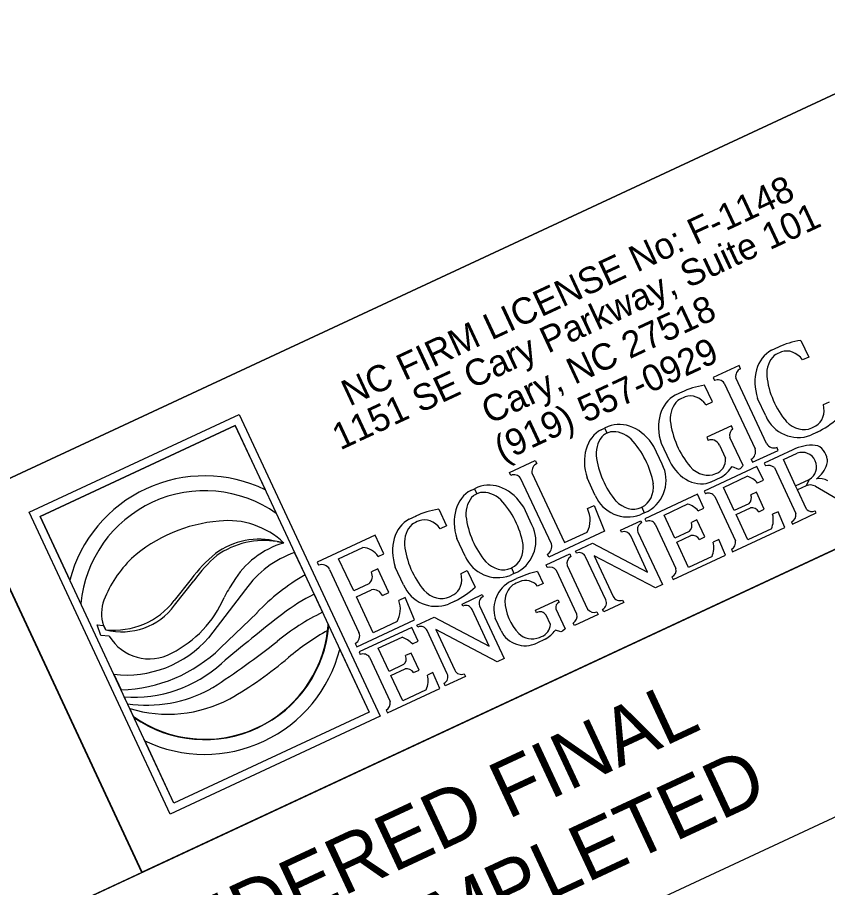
# Model space of a CAD drawing. Extents: x 2216017 to 2218023, y 761241 to 762957.
# Drawn here: x 2217518.1 to 2217596.5, y 762718.7 to 762803 of the extents above; entities that cross this region are included whole.
import ezdxf

# ---------------------------------------------------------------- set-up
doc = ezdxf.new("R2010")
doc.units = 0
for name, color, linetype in [('Exist Horizontal Alignment Tick Label', 7, 'Continuous'), ('Sheet Block Title CELL', 7, 'Continuous'), ('Sheet Plan And Profile CELL', 7, 'Continuous'), ('Sheet Sticker Exception Certification CELL', 7, 'Continuous'), ('Stewart Logo', 7, 'Continuous')]:
    doc.layers.add(name, color=color, linetype=linetype)

msp = doc.modelspace()

# ---------------------------------------------------------------- linework, layer by layer
at = {"layer": 'Sheet Block Title CELL'}
for p, q in [((2217593.973, 762771.693), (2217594.724, 762770.082)), ((2217591.132, 762770.738), (2217591.836, 762771.066)), ((2217594.724, 762770.082), (2217594.128, 762769.804)), ((2217587.978, 762769.257), (2217585.465, 762768.085)), ((2217588.12, 762768.952), (2217587.978, 762769.257)), ((2217585.393, 762765.73), (2217584.642, 762767.342)), ((2217585.465, 762768.085), (2217585.594, 762767.808)), ((2217586.552, 762767.56), (2217589.53, 762761.175)), ((2217590.631, 762761.69), (2217587.654, 762768.074)), ((2217582.505, 762766.714), (2217581.801, 762766.386)), ((2217584.797, 762765.453), (2217585.393, 762765.73)), ((2217590.568, 762764.379), (2217589.775, 762766.08)), ((2217596.146, 762765.477), (2217596.742, 762765.755)), ((2217519.268, 762755.039), (2217539.597, 762764.519)), ((2217539.597, 762764.519), (2217553.231, 762735.281)), ((2217520.314, 762754.648), (2217539.204, 762763.457)), ((2217539.204, 762763.457), (2217520.314, 762754.648)), ((2217539.204, 762763.457), (2217552.161, 762735.67)), ((2217542.118, 762757.208), (2217539.204, 762763.457)), ((2217574.626, 762763.04), (2217574.964, 762763.198)), ((2217575.303, 762763.356), (2217574.964, 762763.198)), ((2217574.964, 762763.198), (2217575.196, 762762.701)), ((2217574.964, 762763.198), (2217575.196, 762762.701)), ((2217587.241, 762763.423), (2217584.851, 762762.309)), ((2217587.39, 762763.102), (2217587.241, 762763.423)), ((2217595.016, 762763.217), (2217595.425, 762763.419)), ((2217584.851, 762762.309), (2217585.001, 762761.988)), ((2217588.366, 762759.561), (2217587.096, 762762.284)), ((2217595.542, 762762.798), (2217594.919, 762762.508)), ((2217580.536, 762759.701), (2217579.743, 762761.402)), ((2217580.444, 762761.728), (2217581.237, 762760.028)), ((2217586.09, 762761.552), (2217586.674, 762760.299)), ((2217589.289, 762759.882), (2217591.777, 762761.042)), ((2217593.196, 762761.095), (2217590.419, 762759.801)), ((2217591.777, 762761.042), (2217591.64, 762761.334)), ((2217592.267, 762760.14), (2217593.591, 762760.758)), ((2217565.741, 762758.888), (2217568.254, 762760.059)), ((2217568.254, 762760.059), (2217568.396, 762759.754)), ((2217589.153, 762760.174), (2217589.289, 762759.882)), ((2217590.419, 762759.801), (2217590.541, 762759.539)), ((2217593.449, 762757.605), (2217592.267, 762760.14)), ((2217565.87, 762758.61), (2217565.741, 762758.888)), ((2217567.93, 762758.877), (2217571.089, 762752.103)), ((2217589.714, 762759.472), (2217584.613, 762757.093)), ((2217587.298, 762759.481), (2217587.92, 762759.203)), ((2217587.92, 762759.203), (2217588.105, 762759.289)), ((2217588.105, 762759.289), (2217588.366, 762759.561)), ((2217590.334, 762758.141), (2217589.714, 762759.472)), ((2217591.4, 762759.365), (2217593.475, 762754.914)), ((2217569.806, 762751.978), (2217566.828, 762758.363)), ((2217574.061, 762756.682), (2217573.268, 762758.382)), ((2217585.276, 762757.989), (2217586.26, 762758.448)), ((2217586.474, 762757.458), (2217588.773, 762758.53)), ((2217589.772, 762757.879), (2217590.334, 762758.141)), ((2217593.449, 762757.605), (2217594.773, 762758.222)), ((2217594.773, 762758.222), (2217594.465, 762757.6)), ((2217594.773, 762758.222), (2217594.465, 762757.6)), ((2217562.021, 762757.163), (2217562.36, 762757.321)), ((2217562.698, 762757.478), (2217562.36, 762757.321)), ((2217562.36, 762757.321), (2217562.592, 762756.823)), ((2217562.36, 762757.321), (2217562.592, 762756.823)), ((2217587.517, 762755.219), (2217586.474, 762757.458)), ((2217593.632, 762757.212), (2217593.449, 762757.605)), ((2217593.632, 762757.212), (2217593.449, 762757.605)), ((2217594.465, 762757.6), (2217593.632, 762757.212)), ((2217594.497, 762755.358), (2217593.632, 762757.212)), ((2217595.376, 762757.558), (2217597.865, 762756.104)), ((2217583.955, 762756.787), (2217578.855, 762754.408)), ((2217584.576, 762755.456), (2217583.955, 762756.787)), ((2217584.613, 762757.093), (2217584.734, 762756.835)), ((2217585.625, 762756.577), (2217587.628, 762752.282)), ((2217589.651, 762756.994), (2217589.119, 762756.745)), ((2217590.421, 762755.341), (2217589.651, 762756.994)), ((2217567.932, 762753.824), (2217567.139, 762755.524)), ((2217573.294, 762755.395), (2217573.953, 762755.702)), ((2217573.953, 762755.702), (2217574.966, 762753.203)), ((2217578.51, 762755.52), (2217578.538, 762755.534)), ((2217578.552, 762755.54), (2217578.793, 762754.988)), ((2217578.552, 762755.54), (2217578.793, 762754.988)), ((2217580.715, 762754.772), (2217583.014, 762755.845)), ((2217588.918, 762755.873), (2217587.517, 762755.219)), ((2217532.902, 762725.801), (2217519.268, 762755.039)), ((2217533.271, 762726.862), (2217520.314, 762754.648)), ((2217520.314, 762754.648), (2217523.2, 762748.458)), ((2217556.057, 762754.382), (2217556.761, 762754.71)), ((2217556.761, 762754.71), (2217556.646, 762754.656)), ((2217558.898, 762755.337), (2217559.649, 762753.726)), ((2217578.793, 762754.988), (2217578.413, 762754.81)), ((2217578.793, 762754.988), (2217579.173, 762755.165)), ((2217581.759, 762752.534), (2217580.715, 762754.772)), ((2217584.013, 762755.194), (2217584.576, 762755.456)), ((2217587.702, 762754.824), (2217589.075, 762755.464)), ((2217588.843, 762752.376), (2217587.702, 762754.824)), ((2217589.896, 762755.096), (2217590.421, 762755.341)), ((2217591.764, 762755.094), (2217591.231, 762754.846)), ((2217592.417, 762753.563), (2217591.764, 762755.094)), ((2217593.154, 762753.907), (2217595.455, 762754.98)), ((2217595.455, 762754.98), (2217595.355, 762755.194)), ((2217576.497, 762753.309), (2217578.453, 762754.221)), ((2217578.453, 762754.221), (2217578.544, 762754.025)), ((2217578.855, 762754.408), (2217578.975, 762754.15)), ((2217579.867, 762753.892), (2217581.87, 762749.597)), ((2217583.893, 762754.309), (2217583.36, 762754.06)), ((2217584.663, 762752.656), (2217583.893, 762754.309)), ((2217593.054, 762754.121), (2217593.154, 762753.907)), ((2217559.649, 762753.726), (2217559.054, 762753.448)), ((2217574.966, 762753.203), (2217569.565, 762750.685)), ((2217571.089, 762752.103), (2217573.286, 762753.127)), ((2217576.589, 762753.113), (2217576.497, 762753.309)), ((2217578.189, 762753.128), (2217580.563, 762748.036)), ((2217583.16, 762753.187), (2217581.759, 762752.534)), ((2217587.359, 762751.205), (2217592.417, 762753.563)), ((2217591.117, 762753.436), (2217588.843, 762752.376)), ((2217543.903, 762752.067), (2217543.276, 762752.201)), ((2217543.276, 762752.201), (2217543.903, 762752.067)), ((2217552.744, 762752.827), (2217547.139, 762750.214)), ((2217553.587, 762751.018), (2217552.744, 762752.827)), ((2217561.457, 762750.805), (2217560.664, 762752.505)), ((2217579.129, 762749.238), (2217577.485, 762752.764)), ((2217581.944, 762752.138), (2217583.316, 762752.779)), ((2217583.085, 762749.691), (2217581.944, 762752.138)), ((2217584.137, 762752.411), (2217584.663, 762752.656)), ((2217586.005, 762752.409), (2217585.473, 762752.161)), ((2217586.659, 762750.878), (2217586.005, 762752.409)), ((2217549.213, 762750.545), (2217551.542, 762751.631)), ((2217572.137, 762751.275), (2217573.79, 762752.047)), ((2217572.228, 762751.079), (2217572.137, 762751.275)), ((2217573.79, 762752.047), (2217579.129, 762749.238)), ((2217587.239, 762751.463), (2217587.359, 762751.205)), ((2217545.96, 762748.97), (2217544.946, 762751.143)), ((2217550.67, 762747.421), (2217549.213, 762750.545)), ((2217553.027, 762750.757), (2217553.587, 762751.018)), ((2217569.295, 762749.95), (2217571.586, 762751.019)), ((2217569.565, 762750.685), (2217569.429, 762750.977)), ((2217571.586, 762751.019), (2217571.704, 762750.766)), ((2217575.073, 762746.551), (2217573.124, 762750.731)), ((2217579.882, 762747.718), (2217573.957, 762750.835)), ((2217573.957, 762750.835), (2217575.796, 762746.89)), ((2217581.601, 762748.52), (2217586.659, 762750.878)), ((2217585.359, 762750.751), (2217583.085, 762749.691)), ((2217547.139, 762750.214), (2217547.278, 762749.917)), ((2217555.493, 762748.024), (2217554.7, 762749.724)), ((2217565.905, 762749.643), (2217565.934, 762749.657)), ((2217565.948, 762749.663), (2217566.188, 762749.11)), ((2217565.948, 762749.663), (2217566.188, 762749.11)), ((2217569.412, 762749.698), (2217569.295, 762749.95)), ((2217571.34, 762749.883), (2217573.304, 762745.672)), ((2217548.33, 762749.508), (2217551.18, 762743.397)), ((2217552.993, 762749.565), (2217552.38, 762749.279)), ((2217554.066, 762747.263), (2217552.993, 762749.565)), ((2217561.071, 762749.122), (2217561.667, 762749.4)), ((2217561.667, 762749.4), (2217562.418, 762747.788)), ((2217566.188, 762749.11), (2217565.808, 762748.933)), ((2217566.188, 762749.11), (2217566.568, 762749.287)), ((2217568.464, 762749.299), (2217569, 762748.148)), ((2217572.276, 762745.175), (2217570.299, 762749.415)), ((2217581.48, 762748.778), (2217581.601, 762748.52)), ((2217534.947, 762748.57), (2217533.3, 762746.483)), ((2217533.336, 762746.03), (2217535.191, 762748.411)), ((2217552.125, 762748.099), (2217550.67, 762747.421)), ((2217565.909, 762748.372), (2217566.444, 762748.621)), ((2217569, 762748.148), (2217568.459, 762747.896)), ((2217580.563, 762748.036), (2217579.882, 762747.718)), ((2217540.203, 762747.561), (2217536.63, 762742.893)), ((2217546.829, 762747.105), (2217547.646, 762745.354)), ((2217550.934, 762746.855), (2217552.389, 762747.533)), ((2217553.453, 762746.977), (2217554.066, 762747.263)), ((2217559.941, 762746.862), (2217560.35, 762747.064)), ((2217561.16, 762746.157), (2217563.116, 762747.069)), ((2217563.116, 762747.069), (2217563.207, 762746.873)), ((2217552.556, 762743.377), (2217550.934, 762746.855)), ((2217555.647, 762746.783), (2217555.039, 762746.5)), ((2217556.566, 762744.631), (2217555.647, 762746.783)), ((2217560.467, 762746.442), (2217559.844, 762746.152)), ((2217568.271, 762745.545), (2217570.443, 762746.557)), ((2217570.443, 762746.557), (2217570.55, 762746.328)), ((2217576.818, 762746.289), (2217574.877, 762745.384)), ((2217576.699, 762746.543), (2217576.818, 762746.289)), ((2217561.251, 762745.961), (2217561.16, 762746.157)), ((2217563.792, 762742.086), (2217562.147, 762745.612)), ((2217562.851, 762745.976), (2217565.226, 762740.884)), ((2217568.378, 762745.315), (2217568.271, 762745.545)), ((2217570.232, 762745.694), (2217571.139, 762743.749)), ((2217574.214, 762745.383), (2217574.332, 762745.13)), ((2217574.877, 762745.384), (2217574.758, 762745.638)), ((2217537.78, 762741.901), (2217541.31, 762745.316)), ((2217550.962, 762742.017), (2217556.566, 762744.631)), ((2217556.799, 762744.123), (2217558.453, 762744.895)), ((2217558.453, 762744.895), (2217563.792, 762742.086)), ((2217564.941, 762743.567), (2217564.375, 762744.781)), ((2217569.715, 762744.175), (2217569.298, 762745.07)), ((2217574.332, 762745.13), (2217572.041, 762744.062)), ((2217526.199, 762743.094), (2217525.851, 762744.132)), ((2217525.851, 762744.132), (2217526.445, 762744.08)), ((2217526.671, 762743.669), (2217526.445, 762744.08)), ((2217526.445, 762744.08), (2217526.671, 762743.669)), ((2217556.292, 762743.887), (2217551.192, 762741.509)), ((2217554.868, 762744.455), (2217552.556, 762743.377)), ((2217556.913, 762742.557), (2217556.292, 762743.887)), ((2217556.891, 762743.927), (2217556.799, 762744.123)), ((2217564.545, 762740.566), (2217558.619, 762743.683)), ((2217558.619, 762743.683), (2217560.459, 762739.738)), ((2217571.139, 762743.749), (2217570.891, 762743.525)), ((2217572.041, 762744.062), (2217571.923, 762744.314)), ((2217527.01, 762743.052), (2217526.199, 762743.094)), ((2217553.052, 762741.873), (2217555.351, 762742.945)), ((2217559.736, 762739.399), (2217557.787, 762743.579)), ((2217568.649, 762742.917), (2217568.86, 762743.001)), ((2217570.723, 762743.447), (2217570.199, 762743.609)), ((2217570.891, 762743.525), (2217570.723, 762743.447)), ((2217550.817, 762742.327), (2217550.962, 762742.017)), ((2217556.35, 762742.294), (2217556.913, 762742.557)), ((2217569.215, 762742.758), (2217568.389, 762742.372)), ((2217549.273, 762741.865), (2217552.161, 762735.67)), ((2217551.192, 762741.509), (2217551.312, 762741.25)), ((2217554.096, 762739.635), (2217553.052, 762741.873)), ((2217556.23, 762741.409), (2217555.697, 762741.161)), ((2217557, 762739.757), (2217556.23, 762741.409)), ((2217552.204, 762740.993), (2217554.207, 762736.697)), ((2217565.226, 762740.884), (2217564.545, 762740.566)), ((2217555.497, 762740.288), (2217554.096, 762739.635)), ((2217554.28, 762739.239), (2217555.653, 762739.879)), ((2217556.474, 762739.512), (2217557, 762739.757)), ((2217558.342, 762739.51), (2217557.809, 762739.261)), ((2217558.996, 762737.979), (2217558.342, 762739.51)), ((2217527.448, 762739.349), (2217528.163, 762737.835)), ((2217555.422, 762736.791), (2217554.28, 762739.239)), ((2217561.48, 762739.137), (2217559.539, 762738.232)), ((2217561.362, 762739.391), (2217561.48, 762739.137)), ((2217553.938, 762735.62), (2217558.996, 762737.979)), ((2217557.696, 762737.852), (2217555.422, 762736.791)), ((2217559.539, 762738.232), (2217559.421, 762738.486)), ((2217528.778, 762736.496), (2217528.466, 762737.166)), ((2217529.353, 762735.264), (2217528.995, 762736.032)), ((2217553.231, 762735.281), (2217532.902, 762725.801)), ((2217552.161, 762735.67), (2217533.271, 762726.862)), ((2217552.161, 762735.67), (2217533.271, 762726.862)), ((2217553.817, 762735.878), (2217553.938, 762735.62)), ((2217533.271, 762726.862), (2217530.41, 762732.997))]:
    msp.add_line(p, q, dxfattribs=at)
for centre, radius, start, end in [((2217588.493, 762768.191), 0.847, 116.12075, 187.92747), ((2217585.916, 762767.075), 0.8, 37.30893, 113.74227), ((2217593.713, 762765.696), 3.409, 202.72337, 290.72862), ((2217592.073, 762769.912), 7.915, 295.99068, 313.21702), ((2217591.353, 762762.127), 0.844, 211.20618, 289.93946), ((2217595.046, 762757.445), 4.093, 85.64607, 116.88413), ((2217595.252, 762760.447), 1.084, 33.14024, 84.43273), ((2217588.731, 762760.904), 0.844, 300.06054, 18.72851), ((2217594.084, 762759.444), 1.403, 299.4241, 110.5759), ((2217594.428, 762759.796), 2.132, 10.58297, 35.67988), ((2217568.769, 762758.994), 0.847, 116.12075, 187.92747), ((2217577.506, 762758.139), 3.409, 299.27138, 27.27663), ((2217593.589, 762760.671), 3.054, 308.30868, 341.19279), ((2217595.529, 762760.023), 1.009, 340.54557, 9.405), ((2217590.816, 762758.694), 0.889, 48.98938, 108.04248), ((2217536.248, 762745.082), 13.488, 64.25416, 165.43722), ((2217566.192, 762757.878), 0.8, 37.30893, 113.74227), ((2217588.023, 762756.287), 2.364, 42.31695, 71.52263), ((2217595.772, 762756.652), 1.649, 61.4512, 100.11922), ((2217594.88, 762756.71), 0.982, 59.70431, 115), ((2217536.248, 762745.082), 12.045, 54.87011, 174.69223), ((2217577.206, 762757.999), 3.409, 202.72337, 290.72862), ((2217585.033, 762756.2), 0.702, 32.52547, 115.21556), ((2217588.413, 762756.448), 0.766, 311.2755, 22.86037), ((2217582.265, 762753.602), 2.364, 42.31695, 71.52263), ((2217589.198, 762754.639), 0.834, 33.27091, 98.51806), ((2217571.077, 762754.268), 2.487, 332.69023, 26.93099), ((2217589.009, 762754.315), 2.284, 337.36137, 13.42705), ((2217592.796, 762754.766), 0.695, 291.81671, 12.25698), ((2217595.027, 762755.807), 0.695, 220.28121, 298.18329), ((2217538.86, 762739.571), 14.667, 94.78512, 131.409), ((2217538.513, 762746.455), 7.781, 46.15126, 96.46785), ((2217564.901, 762752.261), 3.409, 299.27138, 27.27663), ((2217578.854, 762753.383), 0.713, 115.75062, 200.94573), ((2217579.274, 762753.514), 0.702, 32.52547, 115.21556), ((2217582.655, 762753.763), 0.766, 311.2755, 22.86037), ((2217576.854, 762752.469), 0.696, 24.91789, 112.41505), ((2217541.494, 762745.38), 7.05, 75.35831, 126.6336), ((2217541.996, 762744.358), 7.947, 80.73048, 125.15374), ((2217583.44, 762751.953), 0.834, 33.27091, 98.51806), ((2217583.251, 762751.63), 2.284, 337.36137, 13.42705), ((2217586.894, 762752.129), 0.75, 297.36509, 11.76665), ((2217546.193, 762744.054), 8.333, 105.94703, 149.59091), ((2217551.478, 762749.822), 1.81, 31.10841, 87.96506), ((2217569.007, 762751.707), 0.844, 300.06054, 18.72851), ((2217537.495, 762742.138), 11.858, 134.67076, 158.22167), ((2217545.445, 762740.957), 12.968, 128.98209, 144.05119), ((2217546.986, 762739.893), 14.55, 131.10523, 144.16107), ((2217548.158, 762741.959), 9.729, 109.27295, 144.84349), ((2217564.601, 762752.122), 3.409, 202.72337, 290.72862), ((2217572.111, 762750.082), 0.796, 120.76553, 194.44607), ((2217572.494, 762750.436), 0.696, 24.91789, 112.41505), ((2217547.588, 762749.156), 0.822, 25.36228, 112.17361), ((2217569.658, 762748.938), 0.799, 36.6163, 107.89411), ((2217581.136, 762749.444), 0.75, 297.36509, 11.76665), ((2217555.658, 762731.84), 19.685, 119.518, 136.79686), ((2217551.521, 762748.847), 0.961, 308.95151, 26.71522), ((2217570.29, 762740.509), 8.978, 101.73903, 115.36722), ((2217549.738, 762740.896), 13.023, 145.49999, 153.10055), ((2217558.638, 762749.341), 3.409, 202.72337, 290.72862), ((2217567.303, 762745.653), 3.056, 117.14862, 196.57596), ((2217567.401, 762746.365), 2.099, 128.90312, 177.34012), ((2217569.049, 762742.824), 5.965, 112.84839, 119.82308), ((2217567.3, 762746.906), 1.524, 40.48108, 111.82605), ((2217557.002, 762727.432), 22.148, 117.34292, 126.57405), ((2217552.574, 762746.59), 0.961, 23.77933, 101.04849), ((2217556.998, 762753.556), 7.915, 295.99068, 313.21702), ((2217530.021, 762745.254), 3.764, 160.058, 198.18149), ((2217527.461, 762751.023), 7.396, 263.86957, 322.13459), ((2217528.184, 762751.076), 10.826, 296.69632, 336.66704), ((2217552.792, 762745.658), 2.399, 329.89667, 20.53981), ((2217563.517, 762746.231), 0.713, 115.75062, 200.94573), ((2217570.17, 762746.656), 4.87, 182.28071, 223.62041), ((2217570.791, 762745.811), 0.571, 114.91648, 191.84717), ((2217574.442, 762746.258), 0.696, 297.03543, 25.08211), ((2217576.428, 762747.184), 0.696, 204.91789, 292.96457), ((2217528.251, 762749.797), 6.328, 255.53701, 323.46219), ((2217557.564, 762725.105), 22.547, 116.09717, 129.36003), ((2217561.517, 762745.317), 0.696, 24.91789, 112.41505), ((2217568.716, 762744.737), 0.67, 29.75047, 120.35254), ((2217573.952, 762746.135), 0.796, 215.55393, 289.23447), ((2217657.947, 762598.351), 186.006, 127.85343, 130.20923), ((2217571.499, 762744.991), 0.799, 302.10589, 13.3837), ((2217536.248, 762745.082), 12.063, 235.30777, 355.12989), ((2217536.275, 762745.017), 11.96, 353.1944, 355.87724), ((2217557.156, 762743.284), 0.696, 24.91789, 112.41505), ((2217568.361, 762744.264), 1.358, 291.5697, 356.2289), ((2217530.88, 762745.347), 4.5, 210.66616, 298.79825), ((2217528.661, 762749.874), 10.595, 263.42388, 318.77767), ((2217536.275, 762745.017), 11.96, 234.63413, 353.1944), ((2217560.254, 762722.097), 24.675, 119.37453, 130.11181), ((2217550.433, 762743.054), 0.822, 297.82639, 24.63772), ((2217554.602, 762740.702), 2.364, 42.31695, 71.52263), ((2217567.263, 762744.697), 2.583, 205.95183, 295.84129), ((2217567.949, 762744.701), 1.916, 227.11766, 291.43228), ((2217567.396, 762745.855), 3.592, 300.4223, 321.30188), ((2217494.327, 762804.233), 78.748, 302.84485, 308.42277), ((2217527.721, 762752.287), 14.459, 271.75125, 314.08391), ((2217536.248, 762745.082), 13.488, 244.56278, 345.74584), ((2217551.611, 762740.615), 0.702, 32.52547, 115.21556), ((2217554.992, 762740.863), 0.766, 311.2755, 22.86037), ((2217529.382, 762749.77), 12.637, 265.84198, 312.16072), ((2217520.22, 762769.247), 37.179, 299.76476, 310.48222), ((2217555.777, 762739.054), 0.834, 33.27091, 98.51806), ((2217561.09, 762740.032), 0.696, 204.91789, 292.96457), ((2217555.588, 762738.731), 2.284, 337.36137, 13.42705), ((2217559.104, 762739.106), 0.696, 297.03543, 25.08211), ((2217530.635, 762749.251), 12.889, 261.71837, 298.46718), ((2217534.905, 762741.375), 3.93, 298.46718, 302.84485), ((2217532.691, 762748.281), 12.795, 253.20766, 297.89059), ((2217553.472, 762736.544), 0.75, 297.36509, 11.76665)]:
    msp.add_arc(centre, radius, start, end, dxfattribs=at)
for centre, major_axis, ratio, start_param, end_param in [((2217597.09, 762759.647), (-5.312, 11.392), 0.785714, 6.051738, 6.289595), ((2217593.053, 762766.917), (-1.808, 3.877), 0.785714, 0.0375, 1.423769), ((2217592.905, 762768.605), (-0.902, 1.934), 0.785714, 4.982585, 6.22779), ((2217593.084, 762767.865), (-1.242, 2.664), 0.785714, 0.242655, 1.08804), ((2217595.392, 762762.907), (-3.529, 7.569), 0.785714, 6.245633, 6.367364), ((2217596.245, 762767.939), (-2.881, 6.179), 0.785714, 1.17427, 1.895784), ((2217587.759, 762755.296), (-5.312, 11.392), 0.785714, 6.051738, 6.289595), ((2217583.574, 762764.254), (-0.902, 1.934), 0.785714, 4.982585, 6.22779), ((2217583.722, 762762.566), (-1.808, 3.877), 0.785714, 0.0375, 1.423769), ((2217583.753, 762763.514), (-1.242, 2.664), 0.785714, 0.242655, 1.08804), ((2217586.061, 762758.556), (-3.529, 7.569), 0.785714, 6.245633, 6.367364), ((2217594.441, 762765.311), (-0.902, 1.934), 0.785714, 3.196988, 4.442193), ((2217576.995, 762759.429), (1.808, -3.877), 0.785714, 1.717824, 3.104092), ((2217586.914, 762763.588), (-2.881, 6.179), 0.785714, 1.17427, 1.895784), ((2217587.727, 762762.378), (-0.338, 0.724), 0.785714, 6.281728, 7.624421), ((2217593.907, 762765.561), (-1.096, 2.35), 0.812926, 1.956822, 3.148618), ((2217576.547, 762759.22), (-1.808, 3.877), 0.785714, 0.0375, 1.423769), ((2217576.577, 762760.168), (-1.242, 2.664), 0.785714, 0.242655, 1.08804), ((2217578.886, 762755.21), (-3.529, 7.569), 0.785714, 0.027164, 0.084179), ((2217578.563, 762755.06), (3.529, -7.569), 0.785714, 3.057414, 3.114429), ((2217576.249, 762760.014), (1.242, -2.664), 0.785714, 2.053552, 2.898937), ((2217574.16, 762757.641), (2.881, -6.179), 0.785714, 1.245809, 1.967323), ((2217585.457, 762761.171), (-0.396, 0.85), 0.785714, 4.7953, 6.376605), ((2217579.738, 762760.242), (-2.881, 6.179), 0.785714, 1.17427, 1.895784), ((2217583.786, 762761.283), (-1.528, 3.277), 0.785714, 1.587409, 3.156276), ((2217585.101, 762760.574), (-0.803, 1.723), 0.785714, 3.012278, 4.210239), ((2217584.576, 762761.21), (-1.134, 2.432), 0.785714, 1.956822, 3.148618), ((2217583.806, 762762.827), (-2.125, 4.557), 0.785714, 3.23623, 3.600647), ((2217564.39, 762753.551), (1.808, -3.877), 0.785714, 1.717824, 3.104092), ((2217563.942, 762753.342), (-1.808, 3.877), 0.785714, 0.0375, 1.423769), ((2217577.484, 762757.903), (1.096, -2.35), 0.812926, 6.27616, 7.467956), ((2217563.973, 762754.29), (-1.242, 2.664), 0.785714, 0.242655, 1.08804), ((2217566.281, 762749.333), (-3.529, 7.569), 0.785714, 0.027164, 0.084179), ((2217565.958, 762749.182), (3.529, -7.569), 0.785714, 3.057414, 3.114429), ((2217563.644, 762754.137), (1.242, -2.664), 0.785714, 2.053552, 2.898937), ((2217561.556, 762751.763), (2.881, -6.179), 0.785714, 1.245809, 1.967323), ((2217577.4, 762757.864), (-1.096, 2.35), 0.812926, 1.956822, 3.148618), ((2217562.015, 762743.292), (-5.312, 11.392), 0.785714, 6.051738, 6.289595), ((2217567.134, 762754.364), (-2.881, 6.179), 0.785714, 1.17427, 1.895784), ((2217557.978, 762750.561), (-1.808, 3.877), 0.785714, 0.0375, 1.423769), ((2217558.009, 762751.509), (-1.242, 2.664), 0.785714, 0.242655, 1.08804), ((2217560.317, 762746.552), (-3.529, 7.569), 0.785714, 6.245633, 6.367364), ((2217557.83, 762752.249), (-0.902, 1.934), 0.785714, 4.982585, 6.22779), ((2217561.17, 762751.583), (-2.881, 6.179), 0.785714, 1.17427, 1.895784), ((2217564.88, 762752.026), (1.096, -2.35), 0.812926, 6.27616, 7.467956), ((2217564.796, 762751.986), (-1.096, 2.35), 0.812926, 1.956822, 3.148618), ((2217559.366, 762748.955), (-0.902, 1.934), 0.785714, 3.196988, 4.442193), ((2217558.832, 762749.205), (-1.096, 2.35), 0.812926, 1.956822, 3.148618)]:
    msp.add_ellipse(centre, major_axis=major_axis, ratio=ratio, start_param=start_param, end_param=end_param, dxfattribs=at)
at = {"layer": 'Sheet Plan And Profile CELL'}
for points in [[(2217465.745, 762858.39), (2217556.376, 762900.651), (2217603.92, 762798.692), (2217513.289, 762756.43)], [(2217513.289, 762756.43), (2217603.92, 762798.692), (2217620.825, 762762.439), (2217530.194, 762720.178)], [(2217422.613, 762714.147), (2217513.244, 762756.409), (2217530.149, 762720.156), (2217439.518, 762677.895)]]:
    msp.add_lwpolyline(points, close=True, dxfattribs=at)
at = {"layer": 'Sheet Sticker Exception Certification CELL'}
for p, q in [((2217439.529, 762677.9), (2217620.825, 762762.439)), ((2217630.756, 762741.141), (2217449.461, 762656.602))]:
    msp.add_line(p, q, dxfattribs=at)
at = {"layer": 'Stewart Logo'}
msp.add_lwpolyline([(2217513.244, 762756.409), (2217422.613, 762714.147), (2217439.518, 762677.895), (2217530.149, 762720.156)], close=True, dxfattribs=at)

# ---------------------------------------------------------------- texts
at = {"layer": 'Exist Horizontal Alignment Tick Label'}
for s, p in [('NC FIRM LICENSE No: F-1148', (2217550.264, 762765.271)), ('1151 SE Cary Parkway, Suite 101', (2217549.365, 762761.022)), ('Cary, NC 27518', (2217563.809, 762763.536)), ('(919) 557-0929', (2217565.056, 762759.896))]:
    msp.add_text(s, height=2.55075, rotation=25, dxfattribs=at).set_placement(p)
at = {"layer": 'Sheet Sticker Exception Certification CELL'}
for s, p in [('DOCUMENT NOT CONSIDERED FINAL', (2217462.998, 762677.429)), ('UNLESS ALL SIGNATURES COMPLETED', (2217462.121, 762667.31))]:
    msp.add_text(s, height=5.5, rotation=25, dxfattribs=at).set_placement(p)

doc.saveas('drawing.dxf')
